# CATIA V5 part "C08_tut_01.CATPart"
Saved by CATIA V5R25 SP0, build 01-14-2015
Part number: Part1
Bounding box of the stored display mesh (mm): x -175 to 175, y -250 to 250, z -8 to 100
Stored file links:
  E:\ashutosh\Academics\Catia\CATIA V5-6R2013_partfiles\Tutorials_ver_2\C08_tut_01.CATPart
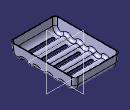
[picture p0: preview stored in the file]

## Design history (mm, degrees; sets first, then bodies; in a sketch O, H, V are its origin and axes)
Body1 (main body)
  Sketch1 on yz-plane, origin (0, 0, 0), H (0, 1, 0), V (0, 0, 1)
    point P1 (-250, 0)
    line L1 (-250, 0) -> (250, 0)
    line L2 (250, 0) -> (250, 100)
    line L3 (250, 100) -> (-250, 100)
    line L4 (-250, 100) -> (-250, 0)
    length L3 = 500
    length L2 = 100
    distance V L2 = 250
    coincidence: P1 H
    horizontal: L1 H, L3 H
    vertical: L2 V, L4 V
  Pad1: profile Sketch1, direction (1, 0, 0), length 175, mirrored extent
  Draft1: Angle -5, Neutral face of Pad1 from Sketch1.L3, PullDir face of Pad1 from Sketch1.L3
  Sketch2 on yz-plane, origin (0, 0, 0), H (0, 1, 0), V (0, 0, 1)
    arc A1 centre (-195.4346, 50) radius 50 from (-245.2443, 45.6422) to (-162.8621, 12.0654) ccw
    reference projected line E1 (-241.2511, 0) -> (-250, 100) from edge [end face of Pad1 | face of Pad1 from Sketch1.L4]
    reference projected line E2 (241.2511, 0) -> (-241.2511, 0) from edge [end face of Pad1 | face of Pad1 from Sketch1.L1]
    arc A2 centre (195.4346, 50) radius 50 from (162.8622, 12.0653) to (245.2443, 45.6422) ccw
    reference projected line E3 (250, 100) -> (241.2511, 0) from edge [end face of Pad1 | face of Pad1 from Sketch1.L2]
    reference projected line E4 (241.2511, 0) -> (-241.2511, 0) from edge [end face of Pad1 | face of Pad1 from Sketch1.L1]
    point P3 (97.7173, 50)
    point P4 (0, 50)
    point P5 (-97.7173, 50)
    construction line L1 (195.4346, 50) -> (-195.4346, 50)
    point P7 (-48.8586, -6.902)
    projected line E5 (250, 100) -> (241.2511, 0) from edge [end face of Pad1 | face of Pad1 from Sketch1.L2]
    projected line E6 (-241.2511, 0) -> (-250, 100) from edge [end face of Pad1 | face of Pad1 from Sketch1.L4]
    arc A3 centre (97.7173, 50) radius 50 from (65.1449, 12.0653) to (130.2898, 12.0654) ccw
    arc A4 centre (0, 50) radius 50 from (-32.5724, 12.0653) to (32.5725, 12.0654) ccw
    arc A5 centre (-97.7173, 50) radius 50 from (-130.2897, 12.0653) to (-65.1448, 12.0654) ccw
    point P23 (-245.2443, 45.6422)
    arc A6 centre (-146.5759, -6.902) radius 25 from (-130.2897, 12.0653) to (-162.8621, 12.0654) ccw
    arc A7 centre (-48.8586, -6.902) radius 25 from (-32.5724, 12.0653) to (-65.1448, 12.0654) ccw
    arc A8 centre (48.8586, -6.902) radius 25 from (65.1449, 12.0653) to (32.5725, 12.0654) ccw
    arc A9 centre (146.5759, -6.902) radius 25 from (162.8622, 12.0653) to (130.2898, 12.0654) ccw
    axis line L2 (146.5759, -6.902) -> (-146.5759, -6.902)
    line L3 (245.2443, 45.6422) -> (237.7725, -39.761)
    line L4 (-245.2443, 45.6422) -> (-237.7725, -39.761)
    line L5 (-237.7725, -39.761) -> (237.7725, -39.761)
    radius A1 = 50
    radius A6 = 25
    radius A5 = 50
    radius A7 = 25
    radius A4 = 50
    radius A8 = 25
    radius A3 = 50
    radius A9 = 25
    tangency: A1 E1, A1 E2, A2 E3, A2 E4, A6 A5, A7 A5, A6 A1, A7 A4, A8 A4, A8 A3, A3 A9, A9 A2, L3 A2, L4 A1
    horizontal: L1 H, L2 H, L5 H
    coincidence: P3 L1, P4 L1, P5 L1, P4 V, E6 P23, L2 P7
  Pocket1: profile Sketch2, direction (-1, 0, 0), through (limit type 3), opposite side length 175
  Fillet1: radius 25, on edge [face of Pocket1 | end face of Pad1]; edge [start face of Pad1 | face of Pad1 from Sketch1.L2]
  Shell1: ExtOffset 0, Face face of Pad1 from Sketch1.L3, IntOffset 5
  Sketch3 on xy-plane, origin (0, 0, 0), H (1, 0, 0), V (0, 1, 0)
    point P1 (0, 195.4)
    line L1 (105, 183.4) -> (-105, 183.4)
    line L2 (-105, 207.4) -> (105, 207.4)
    arc A1 centre (105, 195.4) radius 12 from (105, 183.4) to (105, 207.4) ccw
    point P6 (105, 195.4)
    arc A2 centre (-105, 195.4) radius 12 from (-105, 207.4) to (-105, 183.4) ccw
    point P7 (-105, 195.4)
    point P8 (-105, 207.4)
    axis line L3 (105, 195.4) -> (-105, 195.4)
    reference projected line E1 (175, 250) -> (-175, 250) from edge [face of Pad1 from Sketch1.L2 | face of Pad1 from Sketch1.L3]
    distance P6 P7 = 210
    distance V P7 = 105
    distance L2 L1 = 24
    distance E1 L3 = 54.6
    coincidence: P1 V, A2 P8
    horizontal: L1 H, L2 H, L3 H
    equidistance: L1 L2 P1
    tangency: A1 L1, A2 L2, A1 L2, L1 A2
  Pocket2: profile Sketch3, direction (0, 0, -1), through (limit type 6), opposite side length 25
  RectPattern1: of Pocket2, direction 1 instances 5, spacing 97.7, along edge [end face of Pad1 | face of Pad1 from Sketch1.L3] reversed
  Sketch4 on xy-plane, origin (0, 0, 0), H (1, 0, 0), V (0, 1, 0)
    circle A1 centre (-135, -196) radius 10
    point P1 (-135, -196)
    reference projected line E1 (-175, 250) -> (-175, -250) from edge [start face of Pad1 | face of Pad1 from Sketch1.L3]
    reference projected line E2 (-175, -250) -> (175, -250) from edge [face of Pad1 from Sketch1.L4 | face of Pad1 from Sketch1.L3]
    radius A1 = 10
    distance E1 P1 = 40
    distance P1 E2 = 54
  Pad2: profile Sketch4, direction (0, 0, 1), up to the existing solid (limit type 2), opposite side length 8
  RectPattern2: of Pad2, direction 1 instances 2, spacing 390.8, along edge [start face of Pad1 | face of Pad1 from Sketch1.L3] reversed, direction 2 instances 2, spacing 270, along edge [face of Pad1 from Sketch1.L4 | face of Pad1 from Sketch1.L3]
